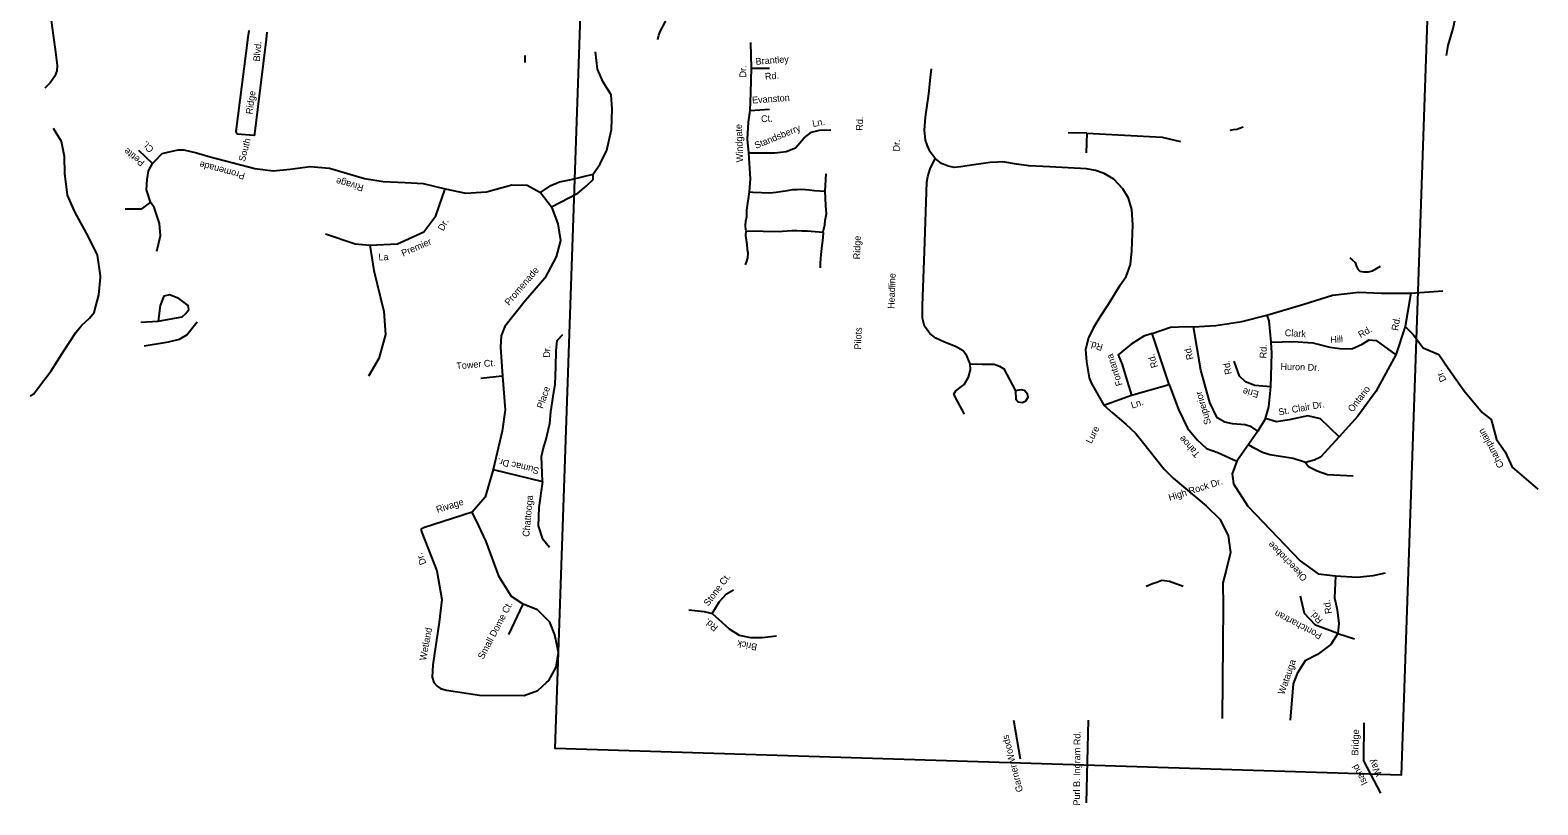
# Model space of a CAD drawing. Extents: x 2308163 to 2335412, y -96774 to 127732.
# Drawn here: x 2322503.8 to 2322561, y 95010.2 to 95039.6 of the extents above; entities that cross this region are included whole.
import ezdxf

# ---------------------------------------------------------------- set-up
doc = ezdxf.new("R2010")
doc.units = 0
for name, color, linetype in [('Old_Level_10', 7, 'Continuous'), ('Old_Level_35', 7, 'Continuous'), ('Old_Level_63', 7, 'Continuous')]:
    doc.layers.add(name, color=color, linetype=linetype)

msp = doc.modelspace()

# ---------------------------------------------------------------- linework, layer by layer
at = {"layer": 'Old_Level_35'}
for p, q in [((2322512.096, 95039.288), (2322512.129, 95039.55)), ((2322512.807, 95039.484), (2322512.775, 95039.221)), ((2322522.594, 95038.342), (2322522.586, 95038.607)), ((2322533.952, 95033.473), (2322533.999, 95034.123))]:
    msp.add_line(p, q, dxfattribs=at)
for points in [[(2322527.622, 95039.216), (2322527.649, 95039.372), (2322527.702, 95039.512), (2322527.866, 95039.814), (2322528.071, 95040.291), (2322528.369, 95041.049), (2322528.645, 95041.831), (2322529.083, 95042.892)], [(2322504.533, 95040.714), (2322504.548, 95040.588), (2322504.653, 95039.746), (2322504.783, 95038.832), (2322504.857, 95038.224), (2322504.85, 95038.02), (2322504.773, 95037.825), (2322504.587, 95037.567), (2322504.392, 95037.37)], [(2322557.504, 95038.605), (2322557.562, 95038.987), (2322557.746, 95039.63), (2322557.851, 95040.113), (2322557.874, 95040.348)], [(2322512.775, 95039.221), (2322512.338, 95035.635), (2322512.336, 95035.602), (2322512.332, 95035.589), (2322512.327, 95035.58), (2322512.318, 95035.576), (2322512.305, 95035.574), (2322511.695, 95035.627), (2322511.672, 95035.641), (2322511.661, 95035.659), (2322511.651, 95035.682), (2322511.648, 95035.701), (2322511.645, 95035.728), (2322512.096, 95039.288)], [(2322531.093, 95033.436), (2322531.131, 95033.936), (2322531.062, 95034.922), (2322531.017, 95035.441), (2322531.052, 95036.083), (2322531.117, 95036.523), (2322531.141, 95037.19), (2322531.16, 95038.123), (2322531.139, 95039.101)], [(2322523.593, 95032.875), (2322524.587, 95033.395), (2322524.899, 95033.662), (2322525.16, 95033.905), (2322525.167, 95034.107), (2322525.433, 95034.501), (2322525.678, 95035.022), (2322525.857, 95035.798), (2322525.884, 95036.579), (2322525.851, 95037.11), (2322525.54, 95037.6), (2322525.33, 95038.087), (2322525.259, 95038.743)], [(2322531.16, 95038.123), (2322531.842, 95038.125)], [(2322538.122, 95034.702), (2322537.933, 95034.96), (2322537.828, 95035.185), (2322537.758, 95035.401), (2322537.717, 95035.773), (2322537.761, 95036.271), (2322537.886, 95037.15), (2322537.949, 95037.773), (2322537.967, 95037.982), (2322537.981, 95038.098)], [(2322531.117, 95036.523), (2322531.851, 95036.573)], [(2322506.499, 95030.26), (2322506.391, 95031.037), (2322506.044, 95031.734), (2322505.521, 95032.678), (2322505.247, 95033.317), (2322505.145, 95034.135), (2322505.131, 95034.783), (2322505.02, 95035.343), (2322504.722, 95035.834)], [(2322531.062, 95034.922), (2322532.052, 95034.914), (2322532.485, 95034.973), (2322532.835, 95035.107), (2322533.163, 95035.487), (2322533.434, 95035.703), (2322533.745, 95035.778), (2322534.172, 95035.786)], [(2322543.872, 95035.66), (2322543.166, 95035.675)], [(2322543.872, 95035.66), (2322543.84, 95034.917)], [(2322543.872, 95035.66), (2322546.731, 95035.509), (2322547.423, 95035.342)], [(2322549.304, 95035.775), (2322549.433, 95035.799), (2322549.554, 95035.819), (2322549.66, 95035.853), (2322549.795, 95035.906)], [(2322508.475, 95034.512), (2322507.955, 95035.012)], [(2322508.387, 95033.053), (2322508.237, 95033.521), (2322508.269, 95033.909), (2322508.317, 95034.24), (2322508.475, 95034.512), (2322508.552, 95034.602), (2322508.84, 95034.889), (2322509.101, 95034.954), (2322509.438, 95035.035), (2322509.66, 95035.027), (2322510.138, 95034.918), (2322510.651, 95034.771)], [(2322510.651, 95034.771), (2322512.349, 95034.324), (2322513.038, 95034.239), (2322513.687, 95034.294), (2322514.445, 95034.406), (2322515.181, 95034.334), (2322516.507, 95033.95), (2322517.208, 95033.834), (2322518.037, 95033.79), (2322518.728, 95033.751), (2322519.553, 95033.553), (2322520.347, 95033.387), (2322521.119, 95033.437), (2322522.082, 95033.712), (2322522.666, 95033.692), (2322523.165, 95033.413), (2322523.593, 95032.875), (2322523.832, 95032.236), (2322523.933, 95031.602), (2322523.758, 95030.978), (2322523.33, 95030.177), (2322522.608, 95029.326), (2322521.82, 95028.338), (2322521.685, 95027.989), (2322521.655, 95027.559), (2322521.725, 95026.465), (2322521.834, 95025.184), (2322521.714, 95024.373), (2322521.372, 95022.924), (2322521.074, 95021.873), (2322520.577, 95021.306), (2322518.741, 95020.723), (2322518.646, 95020.665), (2322518.645, 95020.619), (2322518.673, 95020.541), (2322519.239, 95019.091), (2322519.432, 95018.008), (2322519.326, 95017.15), (2322519.085, 95015.528), (2322519.069, 95015.067), (2322519.124, 95014.865), (2322519.257, 95014.722), (2322519.377, 95014.626), (2322519.606, 95014.572), (2322520.861, 95014.375), (2322522.554, 95014.363), (2322523.069, 95014.56), (2322523.402, 95014.856), (2322523.482, 95014.93), (2322523.761, 95015.444), (2322523.857, 95015.994), (2322523.711, 95016.661), (2322523.527, 95017.144), (2322523.051, 95017.606), (2322522.519, 95017.824), (2322522.068, 95018.117), (2322521.601, 95018.856), (2322521.108, 95020.195), (2322520.836, 95020.789), (2322520.577, 95021.306)], [(2322539.457, 95026.933), (2322539.326, 95027.236), (2322539.19, 95027.419), (2322538.889, 95027.586), (2322538.473, 95027.743), (2322538.145, 95027.9), (2322537.92, 95028.078), (2322537.726, 95028.35), (2322537.641, 95028.652), (2322537.644, 95029.134), (2322537.721, 95031.184), (2322537.812, 95033.802), (2322537.846, 95034.018), (2322537.931, 95034.314), (2322538.122, 95034.702)], [(2322545.123, 95029.889), (2322545.361, 95030.234), (2322545.524, 95030.689), (2322545.571, 95031.207), (2322545.615, 95032.186), (2322545.576, 95032.776), (2322545.444, 95033.202), (2322545.24, 95033.552), (2322544.89, 95033.927), (2322544.534, 95034.135), (2322544.195, 95034.255), (2322543.854, 95034.316), (2322542.473, 95034.393), (2322541.68, 95034.43), (2322541.211, 95034.495), (2322540.694, 95034.572), (2322540.504, 95034.569), (2322540.208, 95034.549), (2322539.585, 95034.469), (2322539.084, 95034.385), (2322538.839, 95034.363), (2322538.617, 95034.411), (2322538.366, 95034.511), (2322538.122, 95034.702)], [(2322523.165, 95033.413), (2322523.562, 95033.683), (2322523.895, 95033.822), (2322524.327, 95033.908), (2322525.167, 95034.107)], [(2322515.024, 95031.845), (2322516.15, 95031.468), (2322516.703, 95031.418), (2322517.751, 95031.474), (2322518.752, 95031.932), (2322519.204, 95032.531), (2322519.553, 95033.553)], [(2322530.956, 95031.988), (2322530.944, 95032.161), (2322530.95, 95032.333), (2322530.987, 95032.51), (2322530.983, 95032.75), (2322531.093, 95033.436)], [(2322531.093, 95033.436), (2322531.222, 95033.431), (2322531.541, 95033.414), (2322531.861, 95033.403), (2322532.096, 95033.426), (2322532.269, 95033.451), (2322532.53, 95033.497), (2322532.734, 95033.527), (2322532.894, 95033.528), (2322533.024, 95033.542), (2322533.214, 95033.529), (2322533.362, 95033.518), (2322533.552, 95033.493), (2322533.952, 95033.473)], [(2322533.886, 95031.924), (2322533.95, 95032.193), (2322533.956, 95032.352), (2322534.002, 95032.609), (2322533.988, 95032.924), (2322533.952, 95033.473)], [(2322508.638, 95031.193), (2322508.77, 95031.781), (2322508.73, 95032.245), (2322508.528, 95032.844), (2322508.387, 95033.053), (2322508.045, 95032.787), (2322507.433, 95032.79)], [(2322530.933, 95030.676), (2322530.99, 95030.818), (2322531.025, 95030.94), (2322531.044, 95031.124), (2322531.011, 95031.26), (2322530.999, 95031.451), (2322530.956, 95031.785), (2322530.968, 95031.963)], [(2322530.98, 95031.969), (2322532.242, 95031.944), (2322532.335, 95031.953), (2322532.699, 95031.977), (2322532.884, 95031.977), (2322533.074, 95031.964), (2322533.271, 95031.964), (2322533.886, 95031.918)], [(2322533.775, 95030.562), (2322533.782, 95030.74), (2322533.788, 95030.917), (2322533.801, 95031.065), (2322533.833, 95031.292), (2322533.885, 95031.715), (2322533.897, 95031.905)], [(2322516.703, 95031.418), (2322516.854, 95030.459), (2322517.232, 95028.908), (2322517.294, 95028.045), (2322517.047, 95027.13), (2322516.655, 95026.467)], [(2322553.84, 95030.936), (2322553.919, 95030.869), (2322554.035, 95030.76), (2322554.092, 95030.614), (2322554.136, 95030.508), (2322554.215, 95030.438), (2322554.362, 95030.409), (2322554.538, 95030.408), (2322554.697, 95030.455), (2322554.994, 95030.621)], [(2322503.833, 95025.719), (2322503.974, 95025.794), (2322504.114, 95025.983), (2322504.625, 95026.665), (2322505.106, 95027.424), (2322505.563, 95028.115), (2322505.789, 95028.389), (2322506.083, 95028.663), (2322506.254, 95028.875), (2322506.439, 95029.54), (2322506.498, 95030.196), (2322506.499, 95030.26)], [(2322545.123, 95029.889), (2322544.677, 95029.169), (2322544.366, 95028.699), (2322544.116, 95028.276), (2322543.934, 95027.909), (2322543.825, 95027.473), (2322543.856, 95027.001), (2322543.961, 95026.401), (2322544.047, 95026.179), (2322544.518, 95025.36), (2322544.841, 95025.068), (2322545.345, 95024.643), (2322545.71, 95024.301), (2322545.981, 95023.978), (2322546.797, 95022.943), (2322547.138, 95022.598), (2322548.397, 95021.554), (2322548.909, 95021.046), (2322549.221, 95020.427), (2322549.317, 95019.777), (2322549.157, 95019.116), (2322549.022, 95018.63), (2322549.031, 95017.747), (2322548.998, 95013.5)], [(2322508.023, 95028.507), (2322508.684, 95028.544), (2322509.592, 95028.713), (2322509.731, 95028.83), (2322509.844, 95028.984), (2322509.824, 95029.143), (2322509.463, 95029.398), (2322509.114, 95029.547), (2322508.902, 95029.488), (2322508.76, 95029.141)], [(2322546.342, 95028.077), (2322547.04, 95028.311), (2322547.663, 95028.346), (2322547.91, 95028.329), (2322548.765, 95028.379), (2322549.745, 95028.537), (2322550.686, 95028.767), (2322552.1, 95029.184), (2322553.183, 95029.534), (2322554.181, 95029.639), (2322555.033, 95029.608), (2322556.15, 95029.598)], [(2322556.15, 95029.598), (2322555.935, 95028.345), (2322555.58, 95027.265), (2322554.819, 95025.875), (2322554.134, 95024.949), (2322553.427, 95024.161), (2322552.725, 95023.399), (2322552.491, 95023.275), (2322552.156, 95023.189), (2322551.689, 95023.341), (2322550.809, 95023.478), (2322550.527, 95023.564), (2322550.243, 95023.718), (2322549.991, 95023.862)], [(2322556.15, 95029.598), (2322557.357, 95029.688)], [(2322508.76, 95029.141), (2322508.684, 95028.544)], [(2322550.859, 95027.744), (2322550.777, 95028.552), (2322550.707, 95028.773)], [(2322508.152, 95027.61), (2322509.08, 95027.767), (2322509.496, 95027.862), (2322509.771, 95028.029), (2322510.165, 95028.518)], [(2322550.355, 95024.376), (2322550.105, 95024.546), (2322549.872, 95024.623), (2322549.386, 95024.656), (2322549.099, 95024.717), (2322548.816, 95024.888), (2322548.528, 95025.468), (2322548.197, 95026.682), (2322547.91, 95028.329)], [(2322555.935, 95028.345), (2322556.234, 95028.037), (2322556.618, 95027.537), (2322557.211, 95027.287), (2322557.565, 95026.76), (2322558.166, 95025.908), (2322558.854, 95025.083), (2322559.189, 95024.814), (2322559.392, 95024.062), (2322559.72, 95023.592), (2322559.987, 95023.011), (2322560.961, 95022.175)], [(2322523.24, 95022.471), (2322523.21, 95023.418), (2322523.285, 95023.752), (2322523.378, 95024.022), (2322523.526, 95024.669), (2322523.563, 95025.109), (2322523.646, 95025.695), (2322523.725, 95026.154), (2322523.747, 95026.805), (2322523.768, 95027.414), (2322523.803, 95027.812), (2322524.021, 95028.036)], [(2322546.996, 95026.147), (2322546.342, 95028.077), (2322546.028, 95027.975), (2322545.557, 95027.677), (2322545.063, 95027.273), (2322545.207, 95026.905), (2322545.347, 95026.43), (2322545.559, 95025.736)], [(2322553.427, 95024.161), (2322552.719, 95024.848), (2322552.251, 95024.955), (2322551.534, 95024.81), (2322551.053, 95024.733), (2322550.646, 95024.856), (2322550.773, 95025.294), (2322550.839, 95026.053), (2322550.887, 95027.336), (2322550.859, 95027.744)], [(2322550.859, 95027.744), (2322551.687, 95027.772), (2322552.44, 95027.729), (2322553.079, 95027.555), (2322553.459, 95027.508), (2322553.908, 95027.501), (2322554.304, 95027.673), (2322554.564, 95027.834), (2322554.835, 95027.816), (2322555.58, 95027.265)], [(2322550.839, 95026.053), (2322550.239, 95026.106), (2322549.885, 95026.25), (2322549.661, 95026.465), (2322549.457, 95027.026)], [(2322520.914, 95026.39), (2322521.724, 95026.477)], [(2322539.234, 95025.026), (2322538.983, 95025.49), (2322538.836, 95025.778), (2322538.903, 95025.901), (2322539.225, 95026.141), (2322539.392, 95026.418), (2322539.465, 95026.698), (2322539.457, 95026.933)], [(2322539.457, 95026.933), (2322539.909, 95026.92), (2322540.357, 95026.909), (2322540.556, 95026.844), (2322540.723, 95026.737), (2322541.164, 95025.903), (2322541.18, 95025.59), (2322541.267, 95025.492), (2322541.43, 95025.461), (2322541.566, 95025.529), (2322541.652, 95025.662), (2322541.622, 95025.785), (2322541.504, 95025.919), (2322541.383, 95025.943), (2322541.226, 95025.922), (2322541.164, 95025.903)], [(2322545.559, 95025.736), (2322546.996, 95026.147)], [(2322546.996, 95026.147), (2322547.343, 95025.193), (2322547.692, 95024.494), (2322548.049, 95024.052), (2322548.41, 95023.725), (2322548.835, 95023.567), (2322549.55, 95023.238)], [(2322544.518, 95025.36), (2322545.559, 95025.736)], [(2322550.646, 95024.856), (2322550.355, 95024.376), (2322549.55, 95023.238), (2322549.38, 95022.758), (2322549.425, 95022.384), (2322549.968, 95021.535), (2322551.96, 95019.461), (2322552.631, 95018.98), (2322553.288, 95018.9), (2322554.117, 95018.843), (2322554.721, 95018.908), (2322555.183, 95019.007)], [(2322552.156, 95023.189), (2322552.27, 95023.045), (2322552.596, 95022.876), (2322552.995, 95022.735), (2322553.963, 95022.686)], [(2322521.372, 95022.924), (2322523.24, 95022.471), (2322523.101, 95021.488), (2322523.077, 95020.795), (2322523.229, 95020.327), (2322523.512, 95019.981)], [(2322546.115, 95018.507), (2322546.362, 95018.614), (2322546.525, 95018.664), (2322546.713, 95018.731), (2322547.005, 95018.692), (2322547.519, 95018.514)], [(2322553.288, 95018.9), (2322553.259, 95018.071), (2322553.358, 95017.609), (2322553.426, 95017.091), (2322553.385, 95016.72), (2322553.112, 95016.3), (2322552.612, 95015.916), (2322552.145, 95015.675), (2322551.842, 95015.198), (2322551.685, 95014.803), (2322551.579, 95013.43)], [(2322529.673, 95017.475), (2322529.95, 95017.928), (2322530.222, 95018.22), (2322530.489, 95018.372)], [(2322553.385, 95016.72), (2322552.535, 95017.025), (2322552.121, 95017.468), (2322551.972, 95018.132)], [(2322521.967, 95016.671), (2322522.519, 95017.824)], [(2322528.792, 95017.606), (2322529.374, 95017.545), (2322529.673, 95017.475), (2322530.044, 95017.14), (2322530.317, 95016.889), (2322530.692, 95016.655), (2322531.131, 95016.559), (2322531.574, 95016.564), (2322532.114, 95016.632)], [(2322553.385, 95016.72), (2322554.008, 95016.516)], [(2322541.362, 95011.957), (2322541.1, 95013.42)], [(2322543.855, 95010.296), (2322543.932, 95013.438)], [(2322555.01, 95010.668), (2322554.364, 95011.893), (2322554.384, 95013.338)]]:
    msp.add_lwpolyline(points, dxfattribs=at)
at = {"layer": 'Old_Level_63'}
msp.add_lwpolyline([(2322557.553, 95062.69), (2322555.782, 95011.346), (2322523.73, 95012.357), (2322525.797, 95072.268)], dxfattribs=at)

# ---------------------------------------------------------------- texts
at = {"layer": 'Old_Level_10'}
for s, height, rotation, p in [('Blvd.', 0.2563, 85.2272, (2322512.538, 95038.372)), ('Brantley', 0.2563, 4.3646, (2322531.331, 95038.251)), ('Dr.', 0.2563, 89.4385, (2322530.964, 95037.772)), ('Rd.', 0.2563, 4.3646, (2322531.684, 95037.685)), ('Ridge', 0.2563, 81.8623, (2322512.253, 95036.366)), ('Evanston', 0.2563, 3.9715, (2322531.195, 95036.786)), ('Ct.', 0.2563, 3.9715, (2322531.536, 95036.074)), ('Ln.', 0.2563, 10.8306, (2322533.495, 95035.895)), ('Rd.', 0.2563, 87.9298, (2322535.377, 95035.753)), ('Windgate', 0.2563, 92.2238, (2322530.852, 95034.568)), ('Standsberry', 0.25632, 22.4236, (2322531.342, 95035.065)), ('Petite', 0.2563, 141.9823, (2322508.195, 95034.586)), ('Ct.', 0.2563, 134.3578, (2322508.539, 95035.073)), ('South ', 0.2563, 75.4775, (2322511.969, 95034.568)), ('Dr.', 0.2563, 87.0673, (2322536.776, 95034.966)), ('Promenade', 0.2563, 164.8185, (2322511.992, 95034.145)), ('Rivage ', 0.2563, 164.9249, (2322516.488, 95033.697)), ('Dr.', 0.2563, 61.5716, (2322519.487, 95031.938)), ('Premier ', 0.2563, 23.573, (2322517.966, 95030.987)), ('Ridge', 0.2563, 88.0247, (2322535.276, 95030.882)), ('La ', 0.2563, 2.8628, (2322517.036, 95030.84)), ('Promenade', 0.2563, 49.5056, (2322521.978, 95029.117)), ('Headline', 0.2563, 88.0247, (2322536.581, 95029.007)), ('Pilots', 0.2563, 87.8633, (2322535.314, 95027.466)), ('Clark', 0.2563, 356.6269, (2322551.365, 95027.981)), ('Rd.', 0.2563, 29.8603, (2322554.244, 95027.897)), ('Rd.', 0.2563, 80.9562, (2322555.664, 95028.17)), ('Dr.', 0.2563, 87.4369, (2322523.525, 95027.154)), ('Rd.', 0.2563, 164.5659, (2322544.501, 95027.66)), ('Rd.', 0.2563, 103.6352, (2322547.915, 95027.113)), ('Rd.', 0.2563, 87.8778, (2322550.672, 95027.131)), ('Hill', 0.2563, 3.1309, (2322553.105, 95027.716)), ('Tower Ct.', 0.2563, 4.9538, (2322519.991, 95026.719)), ('Fontana', 0.2563, 107.7984, (2322545.231, 95026.134)), ('Rd.', 0.2563, 106.6838, (2322546.569, 95026.815)), ('Rd.', 0.2563, 101.3226, (2322549.366, 95026.551)), ('Huron Dr.', 0.2563, 358.0247, (2322551.206, 95026.707)), ('Dr.', 0.2563, 116.2723, (2322557.506, 95026.316)), ('Place', 0.2563, 71.0915, (2322523.26, 95025.211)), ('Superior', 0.2563, 106.4077, (2322548.583, 95024.669)), ('Erie', 0.2563, 167.3506, (2322550.406, 95025.886)), ('Ontario', 0.2563, 52.5914, (2322553.939, 95025.078)), ('Ln.', 0.2563, 18.5093, (2322545.589, 95025.231)), ('St. Clair Dr.', 0.25632, 10.3937, (2322551.154, 95024.971)), ('Lure', 0.2563, 62.5274, (2322544.043, 95023.882)), ('Tahoe', 0.2563, 132.3947, (2322548.178, 95023.518)), ('Champlain', 0.2563, 118.4032, (2322559.687, 95023.064)), ('Sumac Dr.', 0.2563, 166.5432, (2322523.138, 95022.989)), ('High Rock Dr.', 0.25632, 17.5209, (2322547.011, 95021.735)), ('Chattooga', 0.2563, 84.5243, (2322522.74, 95020.368)), ('Rivage ', 0.2563, 17.4763, (2322519.265, 95021.278)), ('Okeechobee', 0.2563, 134.2898, (2322552.242, 95018.839)), ('Dr.', 0.2563, 112.2366, (2322518.851, 95019.373)), ('Stone Ct.', 0.2563, 52.9539, (2322529.529, 95017.729)), ('Small Dome Ct.', 0.25632, 62.207, (2322521.003, 95015.718)), ('Rd.', 0.2563, 99.3895, (2322553.16, 95017.479)), ('Rd.', 0.2563, 140.7679, (2322529.923, 95016.969)), ('Pontchartran', 0.25632, 152.5317, (2322552.805, 95016.703)), ('Rd.', 0.2563, 134.4566, (2322552.831, 95017.24)), ('Wetland', 0.2563, 79.2672, (2322518.833, 95015.676)), ('Brick', 0.2563, 169.0975, (2322531.397, 95016.315)), ('Watauga', 0.2563, 70.8529, (2322551.348, 95014.38)), ('Garner Woods', 0.25632, 104.4911, (2322541.455, 95010.744)), ('Purl B. Ingram Rd.', 0.25632, 89.5734, (2322543.611, 95010.198)), ('Bridge', 0.2563, 88.4171, (2322554.156, 95012.092)), ('Isand', 0.2563, 117.301, (2322554.518, 95011.046)), ('Way', 0.2563, 117.301, (2322555.065, 95011.383))]:
    msp.add_text(s, height=height, rotation=rotation, dxfattribs=at).set_placement(p)

doc.saveas('drawing.dxf')
